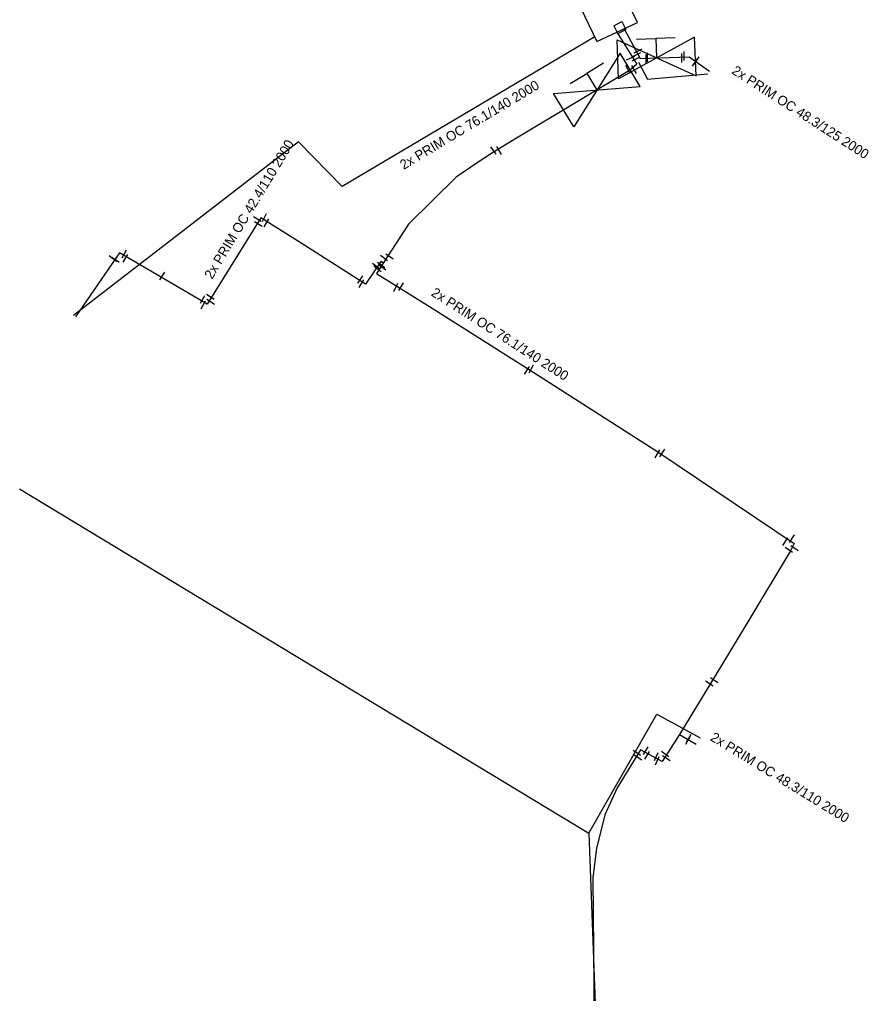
# Model space of a CAD drawing. Extents: x -642943 to -623314, y -1138561 to -1113539.
# Drawn here: x -642031.7 to -641966.1, y -1115362.9 to -1115287.6 of the extents above; entities that cross this region are included whole.
import ezdxf

# ---------------------------------------------------------------- set-up
doc = ezdxf.new("R2010")
doc.units = 0
for name, color, linetype in [('horkovod armatury', 7, 'Continuous'), ('horkovod dimenze', 7, 'Continuous'), ('horkovod předisol', 7, 'Continuous'), ('horkovod sváry', 7, 'Continuous'), ('horkovod trasa', 7, 'Continuous'), ('horkovod zrušený', 7, 'Continuous'), ('horkovod šachty', 7, 'Continuous')]:
    doc.layers.add(name, color=color, linetype=linetype)

# ---------------------------------------------------------------- blocks, each defined once
blk = doc.blocks.new('SPH')
at = {"layer": 'horkovod sváry'}
blk.add_line((0, -0.035), (0, 0.035), dxfattribs=at)
blk = doc.blocks.new('POINT_DISPLAY')
blk.add_line((0, 0), (0, 0))
blk = doc.blocks.new('SCH_01_8')
at = {"layer": 'horkovod armatury'}
for p, q in [((10, 5), (-10, -5)), ((-10, -5), (-10, 5)), ((-10, 5), (10, -5)), ((-5, 5), (0, 5)), ((0, 5), (0, 0)), ((5, 5), (0, 5)), ((10, -5), (10, 5))]:
    blk.add_line(p, q, dxfattribs=at)
blk = doc.blocks.new('SCH_01_9')
at = {"layer": 'horkovod armatury'}
for p, q in [((10, 5), (-10, -5)), ((-10, -5), (-10, 5)), ((-10, 5), (10, -5)), ((-5, 5), (0, 5)), ((0, 5), (0, 0)), ((5, 5), (0, 5)), ((10, -5), (10, 5))]:
    blk.add_line(p, q, dxfattribs=at)

msp = doc.modelspace()

# ---------------------------------------------------------------- linework, layer by layer
at = {"layer": 'horkovod předisol'}
msp.add_line((-641980.689, -1115342.858), (-641979.392, -1115343.6), dxfattribs=at)
for points in [[(-641985.523, -1115288.575), (-641983.972, -1115291.056), (-641984.557, -1115291.544), (-641993.157, -1115296.691), (-641995.05, -1115297.858), (-641996.231, -1115298.631), (-641997.942, -1115299.782), (-642001.618, -1115303.423), (-642003.585, -1115306.433)], [(-641984.965, -1115288.328), (-641983.733, -1115290.617), (-641979.937, -1115290.489), (-641978.369, -1115291.603)], [(-642003.585, -1115306.433), (-642003.752, -1115306.312), (-642004.948, -1115308.054), (-642010.198, -1115304.709), (-642013.041, -1115302.925), (-642017.171, -1115309.609), (-642023.948, -1115305.628), (-642027.351, -1115310.575)], [(-642003.585, -1115306.433), (-642004.098, -1115307.233), (-641999.997, -1115309.789), (-641992.217, -1115314.71), (-641982.445, -1115320.972), (-641971.827, -1115328.096), (-641972.098, -1115328.664), (-641975.489, -1115334.281), (-641977.408, -1115337.481), (-641980.689, -1115342.858)], [(-641980.689, -1115342.858), (-641982.023, -1115344.954), (-641983.688, -1115344.045), (-641985.49, -1115346.984), (-641986.444, -1115349.059), (-641987.095, -1115351.673), (-641987.368, -1115353.915), (-641987.233, -1115370.63), (-641987.202, -1115375.755), (-641987.157, -1115377.982), (-641987.066, -1115382.368), (-641986.945, -1115388.66), (-641986.869, -1115391.379), (-641979.891, -1115395.801)]]:
    msp.add_lwpolyline(points, dxfattribs=at)
at = {"layer": 'horkovod trasa'}
msp.add_line((-641980.689, -1115342.858), (-641979.392, -1115343.6), dxfattribs=at)
for points in [[(-641985.523, -1115288.575), (-641983.972, -1115291.056), (-641984.557, -1115291.544), (-641993.157, -1115296.691), (-641995.05, -1115297.858), (-641996.231, -1115298.631), (-641997.942, -1115299.782), (-642001.618, -1115303.423), (-642003.585, -1115306.433)], [(-641984.965, -1115288.328), (-641983.733, -1115290.617), (-641979.937, -1115290.489), (-641978.369, -1115291.603)], [(-642003.585, -1115306.433), (-642003.752, -1115306.312), (-642004.948, -1115308.054), (-642010.198, -1115304.709), (-642013.041, -1115302.925), (-642017.171, -1115309.609), (-642023.948, -1115305.628), (-642027.351, -1115310.575)], [(-642003.585, -1115306.433), (-642004.098, -1115307.233), (-641999.997, -1115309.789), (-641992.217, -1115314.71), (-641982.445, -1115320.972), (-641971.827, -1115328.096), (-641972.098, -1115328.664), (-641975.489, -1115334.281), (-641977.408, -1115337.481), (-641980.689, -1115342.858)], [(-641980.689, -1115342.858), (-641982.023, -1115344.954), (-641983.688, -1115344.045), (-641985.49, -1115346.984), (-641986.444, -1115349.059), (-641987.095, -1115351.673), (-641987.368, -1115353.915), (-641987.233, -1115370.63), (-641987.202, -1115375.755), (-641987.157, -1115377.982), (-641987.066, -1115382.368), (-641986.945, -1115388.66), (-641986.869, -1115391.379), (-641979.891, -1115395.801)]]:
    msp.add_lwpolyline(points, dxfattribs=at)
at = {"layer": 'horkovod zrušený'}
for points in [[(-641987.237, -1115288.94), (-642006.742, -1115300.511), (-642010.121, -1115297.054), (-642027.504, -1115310.482)], [(-641983.861, -1115290.906), (-641983.154, -1115292.207), (-641978.495, -1115291.8)], [(-642031.675, -1115323.866), (-641987.677, -1115350.477), (-641982.431, -1115341.278), (-641979.085, -1115343.115)], [(-641987.677, -1115350.477), (-641986.199, -1115390.693), (-641979.319, -1115394.99)]]:
    msp.add_lwpolyline(points, dxfattribs=at)
at = {"layer": 'horkovod šachty'}
for p, q in [((-641985.77, -1115288.083), (-641985.146, -1115287.765)), ((-641985.146, -1115287.765), (-641984.828, -1115288.389)), ((-641985.77, -1115288.083), (-641985.452, -1115288.707)), ((-641984.828, -1115288.389), (-641985.452, -1115288.707))]:
    msp.add_line(p, q, dxfattribs=at)
msp.add_lwpolyline([(-641983.938, -1115287.841), (-641985.214, -1115285.187), (-641988.323, -1115286.682), (-641987.066, -1115289.296), (-641983.938, -1115287.841)], dxfattribs=at)

# ---------------------------------------------------------------- block references
at = {"layer": 'horkovod armatury'}
for name, p, xscale, yscale, rotation in [('SCH_01_8', (-641982.459, -1115290.571), 0.3000014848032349, 0.30000148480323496, 2.1349211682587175), ('SCH_01_9', (-641987.068, -1115293.052), 0.29999156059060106, 0.29999156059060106, 31.259659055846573)]:
    msp.add_blockref(name, p, dxfattribs=dict(at, xscale=xscale, yscale=yscale, rotation=rotation))
at = {"layer": 'horkovod sváry'}
for p, xscale, yscale, rotation in [((-641983.987, -1115290.31), 9.999994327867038, 9.999994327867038, -62.806842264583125), ((-641983.887, -1115290.03), 10.000004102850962, 10.00000410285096, -63.368488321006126), ((-641984.457, -1115290.58), 10.00000656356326, 10.000006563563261, -65.09048637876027), ((-641984.027, -1115290.65), 10.000002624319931, 10.000002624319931, -63.37624402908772), ((-641979.497, -1115290.93), 9.999982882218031, 9.999982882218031, -33.27212062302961), ((-641979.357, -1115290.77), 10.000000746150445, 10.000000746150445, -34.28672667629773), ((-641984.657, -1115291.47), 10.00001184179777, 10.000011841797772, 28.6947812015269), ((-641984.187, -1115291.46), 10.000026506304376, 10.000026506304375, 28.962737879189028), ((-641995.057, -1115297.73), 10.000011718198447, 10.000011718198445, 35.901831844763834), ((-641994.627, -1115297.73), 9.99999078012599, 9.99999078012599, 31.304188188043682), ((-642013.307, -1115303.04), 10.000008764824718, 10.000008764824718, 58.433206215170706), ((-642012.747, -1115302.91), 10.000019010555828, 10.00001901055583, -26.875280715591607), ((-642012.587, -1115303.32), 10.00000862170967, 10.000008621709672, -29.53861203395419), ((-642013.227, -1115303.43), 9.999990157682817, 9.999990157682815, 58.252910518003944), ((-642024.457, -1115306.09), 9.999998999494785, 9.999998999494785, 53.237678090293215), ((-642024.247, -1115306.19), 9.999998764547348, 9.999998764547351, 54.100090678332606), ((-642023.572, -1115305.718), 10.000007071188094, 10.00000707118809, -29.350806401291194), ((-642023.484, -1115306.065), 10.000007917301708, 10.00000791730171, -29.475767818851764), ((-642003.507, -1115306.05), 10.000023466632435, 10.000023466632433, 51.55148963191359), ((-642003.087, -1115305.93), 9.999998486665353, 9.999998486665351, 55.55164949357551), ((-642004.127, -1115306.67), 10.000009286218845, 10.000009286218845, 51.94417853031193), ((-642004.017, -1115306.88), 10.000003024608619, 10.000003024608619, 50.94001013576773), ((-642003.737, -1115306.59), 10.000008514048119, 10.000008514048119, 54.76466165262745), ((-642003.657, -1115306.78), 10.000020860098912, 10.000020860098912, 54.46232220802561), ((-642020.631, -1115307.424), 9.99999605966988, 9.999996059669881, -33.3761649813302), ((-642005.347, -1115307.7), 9.999987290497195, 9.999987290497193, -35.13422538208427), ((-642005.257, -1115308.01), 9.999987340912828, 9.999987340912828, -32.132875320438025), ((-642002.597, -1115308.3), 10.000009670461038, 10.000009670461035, -26.475204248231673), ((-642002.187, -1115308.26), 9.999991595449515, 9.999991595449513, -31.58752377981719), ((-642017.517, -1115309.23), 10.000005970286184, 10.000005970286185, -28.28528760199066), ((-642016.937, -1115309.05), 9.99998133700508, 9.999981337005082, 56.50484477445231), ((-642017.477, -1115309.66), 10.000007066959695, 10.000007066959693, -27.362125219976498), ((-642016.897, -1115309.43), 9.999986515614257, 9.999986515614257, 57.12779072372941), ((-641992.127, -1115314.6), 9.999990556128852, 9.999990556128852, -29.726216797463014), ((-641992.467, -1115314.71), 9.999986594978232, 9.999986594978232, -31.364176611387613), ((-641982.387, -1115321.17), 9.999993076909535, 9.999993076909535, -31.64454018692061), ((-641982.007, -1115321.1), 10.000012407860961, 10.000012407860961, -32.80257135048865), ((-641972.507, -1115327.96), 9.999990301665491, 9.999990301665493, -32.05003933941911), ((-641971.987, -1115327.72), 10.000002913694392, 10.000002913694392, -34.19570442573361), ((-641972.237, -1115328.61), 10.000016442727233, 10.000016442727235, 56.92213117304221), ((-641971.807, -1115328.48), 9.999971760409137, 9.999971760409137, 55.89057909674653), ((-641978.007, -1115338.67), 10.000008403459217, 10.000008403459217, 54.797972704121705), ((-641978.377, -1115338.94), 10.000008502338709, 10.000008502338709, 56.19405113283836), ((-641979.957, -1115343.17), 10.0000052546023, 10.0000052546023, -30.273318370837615), ((-641980.037, -1115343.31), 9.999999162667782, 9.999999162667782, -29.427384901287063), ((-641983.987, -1115344.287), 10.000022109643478, 10.000022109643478, 54.76177677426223), ((-641983.885, -1115344.658), 9.999977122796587, 9.999977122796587, 56.473469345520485), ((-641983.291, -1115344.104), 9.999999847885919, 9.999999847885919, -29.846079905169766), ((-641983.188, -1115344.468), 9.999999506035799, 9.999999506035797, -29.55366927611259), ((-641982.483, -1115344.556), 10.000005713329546, 10.000005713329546, -24.222173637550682), ((-641981.794, -1115344.369), 9.999986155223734, 9.999986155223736, 54.508070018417), ((-641982.407, -1115344.892), 9.999982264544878, 9.99998226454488, -23.310907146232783), ((-641981.698, -1115344.709), 10.000007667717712, 10.00000766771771, 55.984116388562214)]:
    msp.add_blockref('SPH', p, dxfattribs=dict(at, xscale=xscale, yscale=yscale, rotation=rotation))
at = {"layer": 'horkovod sváry', "xscale": 10, "yscale": 10}
for p in [(-641983.167, -1115290.54), (-641980.507, -1115290.59), (-641980.317, -1115290.42), (-641983.257, -1115290.67)]:
    msp.add_blockref('SPH', p, dxfattribs=at)
at = {"layer": 'horkovod šachty'}
msp.add_blockref('POINT_DISPLAY', (-641985.299, -1115288.236), dxfattribs=at)

# ---------------------------------------------------------------- texts
at = {"layer": 'horkovod dimenze'}
for s, rotation, p in [('2x PRIM OC 48.3/125 2000', 327.13481, (-641976.714, -1115291.74)), ('2x PRIM OC 76.1/140 2000', 30.98796, (-642002, -1115299.238)), ('2x PRIM OC 42.4/110 2000', 58.8683, (-642016.802, -1115307.734)), ('2x PRIM OC 76.1/140 2000', 327.28767, (-641999.934, -1115308.897)), ('2x PRIM OC 48.3/110 2000', 328.43501, (-641978.369, -1115343.272))]:
    msp.add_text(s, height=0.75, rotation=rotation, dxfattribs=at).set_placement(p)

doc.saveas('drawing.dxf')
